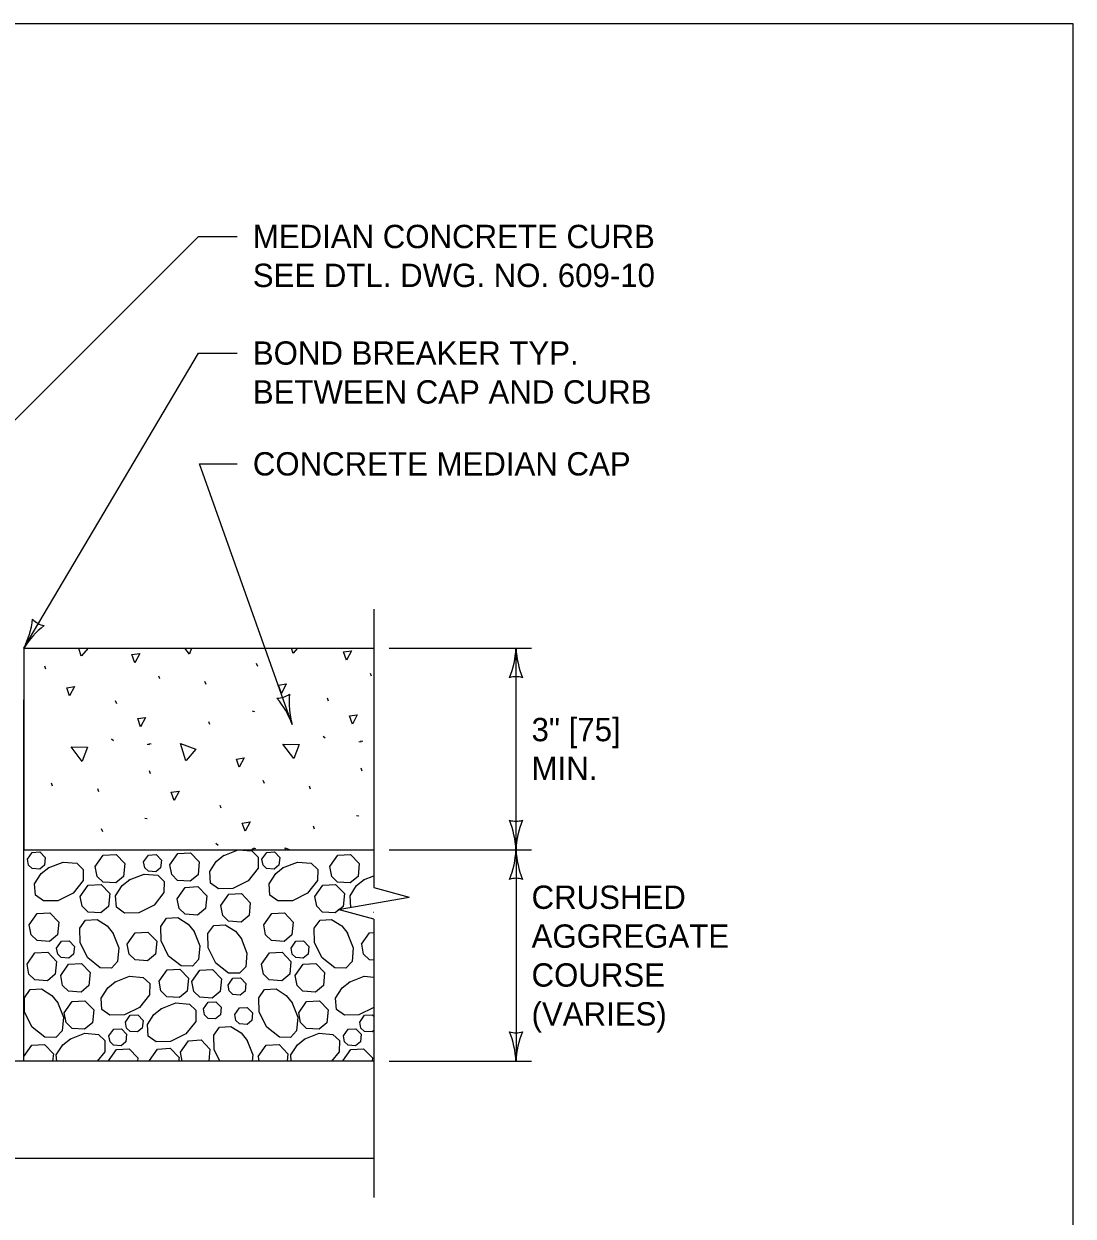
# Model space of a CAD drawing. Extents: x 49991.4 to 50021, y 49987.6 to 50011.4.
# Drawn here: x 50005.916 to 50008.615, y 50008.196 to 50011.263 of the extents above; entities that cross this region are included whole.
import ezdxf

# ---------------------------------------------------------------- set-up
doc = ezdxf.new("R2010")
doc.units = 0
for name, color, linetype in [('Level 1', 7, 'Continuous'), ('Level 2', 7, 'Continuous'), ('Level 3', 7, 'Continuous'), ('Level 6', 7, 'Continuous')]:
    doc.layers.add(name, color=color, linetype=linetype)

msp = doc.modelspace()

# ---------------------------------------------------------------- linework, layer by layer
at = {"layer": 'Level 1'}
for p, q in [((50005.9155, 50009.6569), (50006.8155, 50009.6569)), ((50005.9155, 50009.6569), (50005.9155, 50009.1384)), ((50005.9724, 50009.6029), (50005.9695, 50009.6104)), ((50006.5171, 50009.6097), (50006.5142, 50009.6172)), ((50006.2654, 50009.5778), (50006.2625, 50009.5852)), ((50006.8101, 50009.5846), (50006.8072, 50009.5921)), ((50006.3842, 50009.5634), (50006.3814, 50009.5709)), ((50005.9155, 50008.5943), (50005.9155, 50009.5239)), ((50006.1546, 50009.514), (50006.1517, 50009.5215)), ((50006.6992, 50009.5209), (50006.6964, 50009.5283)), ((50006.5027, 50009.4955), (50006.5085, 50009.4943)), ((50006.3942, 50009.4604), (50006.3913, 50009.4679)), ((50006.1406, 50009.4241), (50006.1463, 50009.4195)), ((50006.6852, 50009.431), (50006.691, 50009.4264)), ((50006.2327, 50009.4104), (50006.2384, 50009.4093)), ((50006.237, 50009.4121), (50006.2427, 50009.411)), ((50006.7773, 50009.4173), (50006.7831, 50009.4161)), ((50006.7816, 50009.419), (50006.7874, 50009.4178)), ((50006.2413, 50009.334), (50006.2385, 50009.3414)), ((50006.786, 50009.3408), (50006.7831, 50009.3483)), ((50005.9896, 50009.302), (50005.9868, 50009.3095)), ((50006.5343, 50009.3089), (50006.5314, 50009.3163)), ((50006.6532, 50009.2945), (50006.6503, 50009.302)), ((50006.1085, 50009.2877), (50006.1056, 50009.2951)), ((50006.4235, 50009.2451), (50006.4206, 50009.2526)), ((50006.227, 50009.2197), (50006.2327, 50009.2186)), ((50006.7716, 50009.2266), (50006.7774, 50009.2254)), ((50006.1185, 50009.1847), (50006.1156, 50009.1922)), ((50006.6631, 50009.1915), (50006.6603, 50009.199)), ((50006.4095, 50009.1552), (50006.4152, 50009.1506)), ((50005.9155, 50009.1384), (50006.8155, 50009.1384)), ((50006.5016, 50009.1415), (50006.5073, 50009.1404)), ((50006.5059, 50009.1432), (50006.5116, 50009.1421)), ((50005.9155, 50008.5943), (50003.7905, 50008.5943)), ((50006.8155, 50008.5943), (50004.4155, 50008.5943)), ((50006.8155, 50008.3444), (50003.6881, 50008.3444))]:
    msp.add_line(p, q, dxfattribs=at)
msp.add_lwpolyline([(50008.6146, 50011.2628), (50000.3356, 50011.2628), (50000.3356, 50000.0624), (50008.6146, 50000.0624)], close=True, dxfattribs=at)
for points in [[(50006.0633, 50009.6363), (50006.057, 50009.6569)], [(50006.0807, 50009.6569), (50006.0639, 50009.6369)], [(50006.2009, 50009.6195), (50006.1934, 50009.6408), (50006.2135, 50009.6436), (50006.2009, 50009.6195)], [(50006.3412, 50009.6417), (50006.3297, 50009.6569)], [(50006.3468, 50009.6569), (50006.3415, 50009.6424)], [(50006.6079, 50009.6432), (50006.6037, 50009.6569)], [(50006.6196, 50009.6569), (50006.6085, 50009.6438)], [(50006.7456, 50009.6264), (50006.7381, 50009.6476), (50006.7582, 50009.6505), (50006.7456, 50009.6264)], [(50006.0333, 50009.534), (50006.0258, 50009.5552), (50006.0459, 50009.5581), (50006.0333, 50009.534)], [(50006.7607, 50009.4617), (50006.7532, 50009.483), (50006.7733, 50009.4859), (50006.7607, 50009.4617)], [(50006.216, 50009.4549), (50006.2085, 50009.4762), (50006.2286, 50009.479), (50006.216, 50009.4549)], [(50006.0654, 50009.3659), (50006.0372, 50009.4033), (50006.079, 50009.4026), (50006.0658, 50009.3667)], [(50006.3322, 50009.3674), (50006.3184, 50009.4122), (50006.3575, 50009.3973), (50006.3328, 50009.368)], [(50006.6101, 50009.3728), (50006.5818, 50009.4101), (50006.6236, 50009.4095), (50006.6104, 50009.3735)], [(50006.4698, 50009.3506), (50006.4623, 50009.3719), (50006.4824, 50009.3747), (50006.4698, 50009.3506)], [(50006.3022, 50009.2651), (50006.2947, 50009.2863), (50006.3148, 50009.2892), (50006.3022, 50009.2651)], [(50006.4849, 50009.186), (50006.4775, 50009.2072), (50006.4976, 50009.2101), (50006.4849, 50009.186)], [(50005.9249, 50009.1142), (50005.9372, 50009.1317), (50005.9568, 50009.1328), (50005.9704, 50009.1186), (50005.9685, 50009.0988), (50005.9564, 50009.0887), (50005.937, 50009.0901), (50005.9279, 50009.099), (50005.9249, 50009.1142)], [(50006.0994, 50009.0955), (50006.1199, 50009.1246), (50006.1526, 50009.1265), (50006.1753, 50009.1029), (50006.172, 50009.0699), (50006.1518, 50009.053), (50006.1195, 50009.0554), (50006.1043, 50009.0701), (50006.0994, 50009.0955)], [(50006.2237, 50009.1075), (50006.236, 50009.1249), (50006.2556, 50009.1261), (50006.2693, 50009.1119), (50006.2673, 50009.0921), (50006.2552, 50009.082), (50006.2358, 50009.0834), (50006.2267, 50009.0922), (50006.2237, 50009.1074)], [(50006.2909, 50009.0999), (50006.3114, 50009.129), (50006.3441, 50009.1309), (50006.3668, 50009.1073), (50006.3635, 50009.0743), (50006.3433, 50009.0575), (50006.311, 50009.0598), (50006.2958, 50009.0745), (50006.2909, 50009.0999)], [(50006.4284, 50009.1232), (50006.4667, 50009.1384), (50006.5019, 50009.1354), (50006.5186, 50009.1194), (50006.5181, 50009.0909), (50006.4927, 50009.0584), (50006.4535, 50009.0388), (50006.4165, 50009.0381), (50006.3956, 50009.0529), (50006.3937, 50009.0824), (50006.4106, 50009.1087), (50006.4299, 50009.1242)], [(50006.528, 50009.1142), (50006.5403, 50009.1317), (50006.5599, 50009.1328), (50006.5736, 50009.1186), (50006.5716, 50009.0988), (50006.5595, 50009.0887), (50006.5401, 50009.0901), (50006.531, 50009.099), (50006.528, 50009.1142)], [(50006.5888, 50009.1384), (50006.5873, 50009.1433), (50006.6002, 50009.1384)], [(50006.7025, 50009.0955), (50006.723, 50009.1246), (50006.7557, 50009.1265), (50006.7784, 50009.1029), (50006.7751, 50009.0699), (50006.7549, 50009.053), (50006.7226, 50009.0554), (50006.7074, 50009.0701), (50006.7025, 50009.0955)], [(50005.978, 50009.0917), (50006.0163, 50009.1069), (50006.0515, 50009.1039), (50006.0683, 50009.088), (50006.0677, 50009.0594), (50006.0423, 50009.0269), (50006.0031, 50009.0073), (50005.9661, 50009.0067), (50005.9453, 50009.0215), (50005.9433, 50009.0509), (50005.9602, 50009.0773), (50005.9795, 50009.0927)], [(50006.5811, 50009.0917), (50006.6194, 50009.1069), (50006.6546, 50009.1039), (50006.6714, 50009.088), (50006.6708, 50009.0594), (50006.6454, 50009.0269), (50006.6062, 50009.0073), (50006.5692, 50009.0067), (50006.5484, 50009.0215), (50006.5464, 50009.0509), (50006.5633, 50009.0773), (50006.5826, 50009.0927)], [(50006.1862, 50009.0607), (50006.2246, 50009.0759), (50006.2598, 50009.0729), (50006.2765, 50009.057), (50006.276, 50009.0284), (50006.2506, 50008.9959), (50006.2113, 50008.9763), (50006.1743, 50008.9757), (50006.1535, 50008.9905), (50006.1515, 50009.0199), (50006.1684, 50009.0463), (50006.1878, 50009.0617)], [(50006.7566, 50008.9902), (50006.7546, 50009.0199), (50006.7715, 50009.0463), (50006.7909, 50009.0617)], [(50006.7893, 50009.0607), (50006.8155, 50009.0711)], [(50006.0608, 50009.0183), (50006.0813, 50009.0475), (50006.114, 50009.0494), (50006.1368, 50009.0258), (50006.1335, 50008.9927), (50006.1133, 50008.9759), (50006.081, 50008.9783), (50006.0658, 50008.993), (50006.0608, 50009.0183)], [(50006.3101, 50009.0126), (50006.3306, 50009.0418), (50006.3633, 50009.0436), (50006.3861, 50009.0201), (50006.3828, 50008.987), (50006.3626, 50008.9702), (50006.3303, 50008.9725), (50006.3151, 50008.9873), (50006.3102, 50009.0126)], [(50006.4222, 50008.9948), (50006.4427, 50009.0239), (50006.4754, 50009.0258), (50006.4981, 50009.0022), (50006.4948, 50008.9692), (50006.4746, 50008.9524), (50006.4423, 50008.9547), (50006.4271, 50008.9694), (50006.4222, 50008.9948)], [(50006.6639, 50009.0183), (50006.6844, 50009.0475), (50006.7171, 50009.0494), (50006.7399, 50009.0258), (50006.7366, 50008.9927), (50006.7273, 50008.985)], [(50006.726, 50008.9839), (50006.7164, 50008.9759), (50006.6841, 50008.9783), (50006.6689, 50008.993), (50006.6639, 50009.0183)], [(50005.9294, 50008.9452), (50005.9499, 50008.9744), (50005.9826, 50008.9762), (50006.0054, 50008.9526), (50006.0021, 50008.9196), (50005.9819, 50008.9028), (50005.9496, 50008.9051), (50005.9344, 50008.9199), (50005.9294, 50008.9452)], [(50006.3528, 50008.9296), (50006.368, 50008.8913), (50006.3649, 50008.856), (50006.349, 50008.8393), (50006.3204, 50008.8398), (50006.288, 50008.8652), (50006.2684, 50008.9045), (50006.2677, 50008.9415), (50006.2825, 50008.9623), (50006.312, 50008.9643), (50006.3383, 50008.9474), (50006.3538, 50008.928)], [(50006.5325, 50008.9452), (50006.553, 50008.9744), (50006.5857, 50008.9762), (50006.6085, 50008.9526), (50006.6052, 50008.9196), (50006.585, 50008.9028), (50006.5527, 50008.9051), (50006.5375, 50008.9199), (50006.5325, 50008.9452)], [(50006.8155, 50008.9769), (50006.8152, 50008.9767)], [(50006.1445, 50008.9246), (50006.1597, 50008.8863), (50006.1567, 50008.8511), (50006.1408, 50008.8343), (50006.1122, 50008.8349), (50006.0797, 50008.8603), (50006.0601, 50008.8995), (50006.0594, 50008.9365), (50006.0742, 50008.9574), (50006.1037, 50008.9593), (50006.1301, 50008.9424), (50006.1455, 50008.9231)], [(50006.4743, 50008.911), (50006.4895, 50008.8727), (50006.4864, 50008.8374), (50006.4705, 50008.8207), (50006.4419, 50008.8212), (50006.4095, 50008.8466), (50006.3899, 50008.8859), (50006.3892, 50008.9229), (50006.404, 50008.9437), (50006.4335, 50008.9457), (50006.4598, 50008.9288), (50006.4753, 50008.9095)], [(50006.7476, 50008.9246), (50006.7628, 50008.8863), (50006.7598, 50008.8511), (50006.7439, 50008.8343), (50006.7153, 50008.8349), (50006.6828, 50008.8603), (50006.6632, 50008.8995), (50006.6626, 50008.9365), (50006.6774, 50008.9574), (50006.7068, 50008.9593), (50006.7332, 50008.9424), (50006.7486, 50008.9231)], [(50005.9998, 50008.8855), (50006.0121, 50008.903), (50006.0318, 50008.9041), (50006.0454, 50008.8899), (50006.0434, 50008.8701), (50006.0313, 50008.86), (50006.0119, 50008.8614), (50006.0028, 50008.8703), (50005.9998, 50008.8855)], [(50006.1813, 50008.8956), (50006.2018, 50008.9248), (50006.2345, 50008.9266), (50006.2573, 50008.9031), (50006.254, 50008.87), (50006.2338, 50008.8532), (50006.2015, 50008.8555), (50006.1863, 50008.8703), (50006.1814, 50008.8956)], [(50006.6029, 50008.8855), (50006.6152, 50008.903), (50006.6349, 50008.9041), (50006.6485, 50008.8899), (50006.6465, 50008.8701), (50006.6344, 50008.86), (50006.615, 50008.8614), (50006.6059, 50008.8703), (50006.603, 50008.8855)], [(50006.7844, 50008.8956), (50006.8049, 50008.9248), (50006.8155, 50008.9254)], [(50005.9237, 50008.844), (50005.9442, 50008.8731), (50005.9769, 50008.875), (50005.9996, 50008.8514), (50005.9963, 50008.8184), (50005.9761, 50008.8016), (50005.9438, 50008.8039), (50005.9286, 50008.8187), (50005.9237, 50008.844)], [(50006.5268, 50008.844), (50006.5473, 50008.8731), (50006.58, 50008.875), (50006.6027, 50008.8514), (50006.5994, 50008.8184), (50006.5792, 50008.8016), (50006.5469, 50008.8039), (50006.5317, 50008.8187), (50006.5268, 50008.844)], [(50006.8155, 50008.8548), (50006.8046, 50008.8555), (50006.7894, 50008.8703), (50006.7845, 50008.8956)], [(50006.0103, 50008.8151), (50006.0308, 50008.8442), (50006.0635, 50008.8461), (50006.0862, 50008.8225), (50006.0829, 50008.7894), (50006.0627, 50008.7726), (50006.0304, 50008.775), (50006.0152, 50008.7897), (50006.0103, 50008.815)], [(50006.6134, 50008.8151), (50006.6339, 50008.8442), (50006.6666, 50008.8461), (50006.6893, 50008.8225), (50006.686, 50008.7894), (50006.6658, 50008.7726), (50006.6335, 50008.775), (50006.6183, 50008.7897), (50006.6134, 50008.815)], [(50006.149, 50008.7979), (50006.1874, 50008.8131), (50006.2226, 50008.8101), (50006.2393, 50008.7942), (50006.2388, 50008.7656), (50006.2134, 50008.7331), (50006.1741, 50008.7135), (50006.1371, 50008.7129), (50006.1163, 50008.7277), (50006.1143, 50008.7571), (50006.1312, 50008.7835), (50006.1506, 50008.7989)], [(50006.2633, 50008.8006), (50006.2838, 50008.8298), (50006.3165, 50008.8316), (50006.3393, 50008.808), (50006.336, 50008.775), (50006.3158, 50008.7582), (50006.2835, 50008.7605), (50006.2683, 50008.7753), (50006.2634, 50008.8006)], [(50006.3476, 50008.7994), (50006.3681, 50008.8285), (50006.4008, 50008.8304), (50006.4236, 50008.8068), (50006.4203, 50008.7738), (50006.4001, 50008.7569), (50006.3678, 50008.7593), (50006.3526, 50008.774), (50006.3477, 50008.7994)], [(50006.4409, 50008.7904), (50006.4532, 50008.8078), (50006.4728, 50008.809), (50006.4864, 50008.7948), (50006.4845, 50008.775), (50006.4723, 50008.7649), (50006.453, 50008.7663), (50006.4438, 50008.7752), (50006.4409, 50008.7904)], [(50006.7522, 50008.7979), (50006.7905, 50008.8131), (50006.8155, 50008.811)], [(50006.002, 50008.7461), (50006.0172, 50008.7078), (50006.0141, 50008.6726), (50005.9982, 50008.6558), (50005.9696, 50008.6564), (50005.9372, 50008.6818), (50005.9175, 50008.721), (50005.9169, 50008.758), (50005.9317, 50008.7788), (50005.9612, 50008.7808), (50005.9875, 50008.7639), (50006.003, 50008.7446)], [(50006.6051, 50008.7461), (50006.6203, 50008.7078), (50006.6172, 50008.6726), (50006.6013, 50008.6558), (50006.5727, 50008.6564), (50006.5403, 50008.6818), (50006.5207, 50008.721), (50006.52, 50008.758), (50006.5348, 50008.7788), (50006.5643, 50008.7808), (50006.5906, 50008.7639), (50006.6061, 50008.7446)], [(50006.8155, 50008.7327), (50006.7772, 50008.7135), (50006.7403, 50008.7129), (50006.7194, 50008.7277), (50006.7175, 50008.7571), (50006.7344, 50008.7835), (50006.7537, 50008.7989)], [(50006.0194, 50008.7192), (50006.0399, 50008.7483), (50006.0726, 50008.7502), (50006.0953, 50008.7266), (50006.092, 50008.6935), (50006.0718, 50008.6767), (50006.0395, 50008.6791), (50006.0243, 50008.6938), (50006.0194, 50008.7192)], [(50006.3774, 50008.7289), (50006.3897, 50008.7464), (50006.4094, 50008.7475), (50006.423, 50008.7333), (50006.421, 50008.7135), (50006.4089, 50008.7034), (50006.3895, 50008.7048), (50006.3804, 50008.7137), (50006.3775, 50008.7289)], [(50006.6225, 50008.7192), (50006.643, 50008.7483), (50006.6757, 50008.7502), (50006.6984, 50008.7266), (50006.6952, 50008.6935), (50006.6749, 50008.6767), (50006.6426, 50008.6791), (50006.6274, 50008.6938), (50006.6225, 50008.7192)], [(50006.268, 50008.7295), (50006.3063, 50008.7447), (50006.3415, 50008.7416), (50006.3583, 50008.7257), (50006.3577, 50008.6971), (50006.3323, 50008.6647), (50006.2931, 50008.645), (50006.2561, 50008.6444), (50006.2352, 50008.6592), (50006.2333, 50008.6887), (50006.2502, 50008.715), (50006.2695, 50008.7304)], [(50006.4582, 50008.7145), (50006.4705, 50008.7319), (50006.4901, 50008.7331), (50006.5037, 50008.7189), (50006.5018, 50008.6991), (50006.4896, 50008.689), (50006.4703, 50008.6904), (50006.4611, 50008.6992), (50006.4582, 50008.7144)], [(50006.1766, 50008.6952), (50006.1889, 50008.7127), (50006.2086, 50008.7138), (50006.2222, 50008.6997), (50006.2202, 50008.6799), (50006.2081, 50008.6698), (50006.1887, 50008.6712), (50006.1796, 50008.68), (50006.1766, 50008.6952)], [(50006.4197, 50008.5944), (50006.4047, 50008.6243), (50006.4041, 50008.6613), (50006.4189, 50008.6822), (50006.4483, 50008.6841), (50006.4747, 50008.6672), (50006.4901, 50008.6479)], [(50006.7797, 50008.6952), (50006.792, 50008.7127), (50006.8117, 50008.7138), (50006.8155, 50008.7098)], [(50006.8155, 50008.6734), (50006.8112, 50008.6698), (50006.7918, 50008.6712), (50006.7827, 50008.68), (50006.7798, 50008.6952)], [(50006.0337, 50008.6514), (50006.0721, 50008.6666), (50006.1073, 50008.6635), (50006.124, 50008.6476), (50006.1235, 50008.619), (50006.1042, 50008.5944)], [(50006.1344, 50008.6597), (50006.1467, 50008.6772), (50006.1663, 50008.6783), (50006.1799, 50008.6642), (50006.178, 50008.6443), (50006.1658, 50008.6342), (50006.1464, 50008.6356), (50006.1373, 50008.6445), (50006.1344, 50008.6597)], [(50006.6368, 50008.6514), (50006.6752, 50008.6666), (50006.7104, 50008.6635), (50006.7271, 50008.6476), (50006.7266, 50008.619), (50006.7073, 50008.5944)], [(50006.7375, 50008.6597), (50006.7498, 50008.6772), (50006.7694, 50008.6783), (50006.783, 50008.6642), (50006.7811, 50008.6443), (50006.7689, 50008.6342), (50006.7495, 50008.6356), (50006.7404, 50008.6445), (50006.7375, 50008.6597)], [(50005.9155, 50008.6064), (50005.936, 50008.6356), (50005.9688, 50008.6374), (50005.9915, 50008.6139), (50005.9896, 50008.5944)], [(50006.0001, 50008.5944), (50005.999, 50008.6106), (50006.0159, 50008.6369), (50006.0353, 50008.6524)], [(50006.133, 50008.5956), (50006.1535, 50008.6248), (50006.1862, 50008.6266), (50006.2089, 50008.6031), (50006.2081, 50008.5944)], [(50006.2387, 50008.5968), (50006.2592, 50008.626), (50006.2919, 50008.6278), (50006.3147, 50008.6043), (50006.3137, 50008.5944)], [(50006.3182, 50008.6182), (50006.3387, 50008.6474), (50006.3714, 50008.6492), (50006.3941, 50008.6256), (50006.391, 50008.5944)], [(50006.4891, 50008.6494), (50006.5043, 50008.6111), (50006.5029, 50008.5944)], [(50006.5186, 50008.6064), (50006.5391, 50008.6356), (50006.5719, 50008.6374), (50006.5946, 50008.6139), (50006.5927, 50008.5944)], [(50006.6032, 50008.5944), (50006.6021, 50008.6106), (50006.619, 50008.6369), (50006.6384, 50008.6524)], [(50006.7361, 50008.5956), (50006.7566, 50008.6248), (50006.7893, 50008.6266), (50006.812, 50008.6031), (50006.8112, 50008.5944)], [(50006.1332, 50008.5944), (50006.133, 50008.5956)], [(50006.2392, 50008.5944), (50006.2387, 50008.5968)], [(50006.3228, 50008.5944), (50006.3182, 50008.6182)], [(50006.521, 50008.5944), (50006.5187, 50008.6064)], [(50006.7364, 50008.5944), (50006.7361, 50008.5956)]]:
    msp.add_lwpolyline(points, dxfattribs=at)
at = {"layer": 'Level 3'}
for p, q in [((50005.3054, 50009.6568), (50006.3644, 50010.7158)), ((50006.3644, 50010.7159), (50006.4644, 50010.7159)), ((50005.9155, 50009.6569), (50006.3644, 50010.4161)), ((50006.3644, 50010.4161), (50006.4645, 50010.4161)), ((50006.6058, 50009.461), (50006.367, 50010.1311)), ((50006.367, 50010.1311), (50006.4645, 50010.1311)), ((50006.8555, 50009.6569), (50007.2215, 50009.6569)), ((50007.1815, 50009.1384), (50007.1815, 50009.6569)), ((50006.8555, 50009.1384), (50007.2215, 50009.1384)), ((50007.1815, 50009.1384), (50007.1815, 50008.5944)), ((50006.8555, 50008.5944), (50007.2215, 50008.5944))]:
    msp.add_line(p, q, dxfattribs=at)
msp.add_lwpolyline([(50006.5779, 50009.5408), (50006.5705, 50009.5621), (50006.5906, 50009.5649), (50006.5779, 50009.5408)], dxfattribs=at)
for centre, radius, start, end in [((50005.707, 50009.7608), 0.233, 333.5234, 352.7732), ((50005.9783, 50009.7687), 0.0548, 222.8349, 258.5572), ((50006.1048, 50009.5402), 0.2223, 128.1521, 148.3356), ((50006.9593, 50009.6661), 0.2223, 337.456, 357.6395), ((50007.4142, 50009.6684), 0.233, 182.8273, 202.0772), ((50007.1815, 50009.5287), 0.0548, 72.1388, 107.8612), ((50006.5668, 50009.5831), 0.0548, 269.8636, 305.586), ((50006.3876, 50009.3792), 0.233, 20.5521, 39.8019), ((50006.8202, 50009.5199), 0.2223, 175.1808, 195.3643), ((50007.1815, 50009.2666), 0.0548, 252.1388, 287.8612), ((50006.9487, 50009.1269), 0.233, 2.8273, 22.0772), ((50007.4036, 50009.1292), 0.2223, 157.456, 177.6395), ((50006.9593, 50009.1475), 0.2223, 337.456, 357.6395), ((50007.4142, 50009.1499), 0.233, 182.8273, 202.0772), ((50007.1815, 50009.0102), 0.0548, 72.1388, 107.8612), ((50007.1815, 50008.7226), 0.0548, 252.1388, 287.8612), ((50006.9487, 50008.5829), 0.233, 2.8273, 22.0772), ((50007.4036, 50008.5852), 0.2223, 157.456, 177.6395)]:
    msp.add_arc(centre, radius, start, end, dxfattribs=at)
at = {"layer": 'Level 6'}
for p, q in [((50006.8155, 50009.7569), (50006.8155, 50009.0412)), ((50006.8155, 50009.0412), (50006.9069, 50009.0168)), ((50006.7241, 50008.9844), (50006.9069, 50009.0168)), ((50006.8155, 50008.9602), (50006.7241, 50008.9844)), ((50006.8155, 50008.9602), (50006.8155, 50008.2444))]:
    msp.add_line(p, q, dxfattribs=at)

# ---------------------------------------------------------------- texts
at = {"layer": 'Level 2'}
for s, p in [('MEDIAN CONCRETE CURB', (50006.5044, 50010.6859)), ('SEE DTL. DWG. NO. 609-10', (50006.5044, 50010.5859)), ('BOND BREAKER TYP.', (50006.5045, 50010.3861)), ('BETWEEN CAP AND CURB', (50006.5045, 50010.2861)), ('CONCRETE MEDIAN CAP', (50006.5045, 50010.1011)), ('3" [75]', (50007.2215, 50009.4176)), ('MIN.', (50007.2215, 50009.3176)), ('CRUSHED', (50007.2215, 50008.9864)), ('AGGREGATE', (50007.2215, 50008.8864)), ('COURSE ', (50007.2215, 50008.7864)), ('(VARIES)', (50007.2215, 50008.6864))]:
    msp.add_text(s, height=0.06, dxfattribs=at).set_placement(p)

doc.saveas('drawing.dxf')
